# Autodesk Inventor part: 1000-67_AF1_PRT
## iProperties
Created: 2007-03
Part Number: 1000-67_AF1_PRT
Document SubType Name: Modeling
Designer: Andy Moles
Material: Steel
Mass: 1.91353 g
Surface Area: 2.52707 cm^2
Volume: 0.243761 cm^3
Density: 7.85 g/cm^3
Author: Andy Moles
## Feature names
1. Base1
